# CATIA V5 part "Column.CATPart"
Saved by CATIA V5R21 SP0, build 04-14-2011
Part number: Column
Bounding box of the stored display mesh (mm): x -75 to 75, y -75 to 75, z -500 to 500
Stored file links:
  D:\CATIA V5R21 E-RESOURCES\CATIA-V5R21\catia-v5r21-prt\c16-catia-v5r20-prt\Revolute_Joint-(Fig 16-3)\Cat_V5R21_Column.CATPart
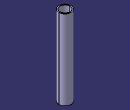
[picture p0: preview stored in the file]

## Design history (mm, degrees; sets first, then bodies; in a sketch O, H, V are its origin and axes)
Body1 (main body)
  Sketch1 on xy-plane, origin (0, 0, 0), H (1, 0, 0), V (0, 1, 0)
    circle A1 centre (0, 0) radius 62.5
    circle A2 centre (0, 0) radius 75
    radius A2 = 75
    radius A1 = 62.5
  Pad1: profile Sketch1, direction (0, 0, 1), length 500, mirrored extent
